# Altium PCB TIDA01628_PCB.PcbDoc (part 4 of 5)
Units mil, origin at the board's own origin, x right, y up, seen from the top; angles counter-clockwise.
Board outline 14212.6 x 5944.88 mil, 4 copper layers (Top Layer, GND, 5V, Bottom Layer), stack 60.8 mil thick; 304 components, 201 nets, 839 pads, 2143 vias.
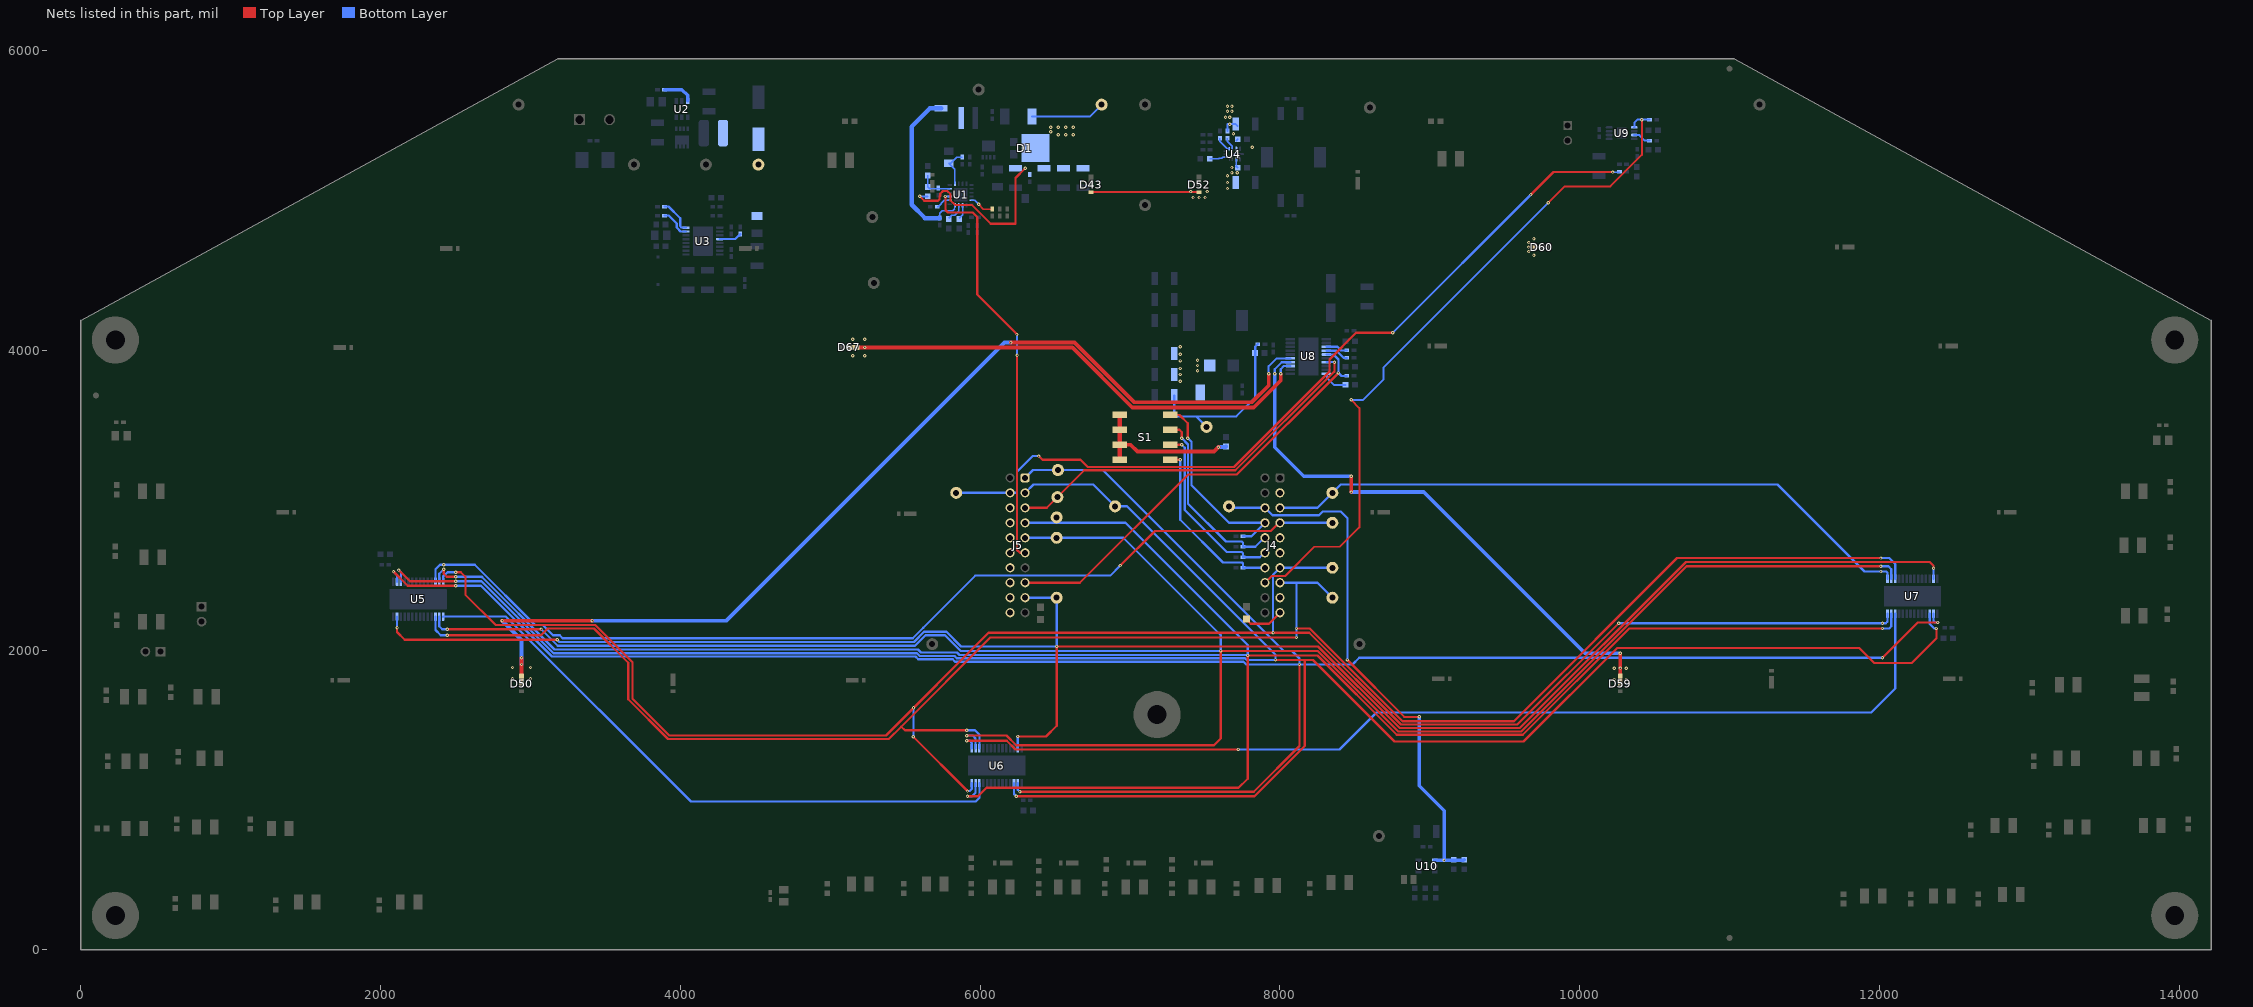
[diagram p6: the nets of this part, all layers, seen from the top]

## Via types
v1: diameter 22, hole 10, Top Layer to Bottom Layer, 1391 vias
v2: diameter 22, hole 10, Top Layer to Bottom Layer, tented both sides, 644 vias
v3: diameter 19.68, hole 7.87, Top Layer to Bottom Layer, tented both sides, 56 vias
v4: diameter 19.68, hole 7.87, Top Layer to Bottom Layer, 47 vias
v5: diameter 19.68, hole 7.87, Top Layer to Bottom Layer, tented top, 5 vias

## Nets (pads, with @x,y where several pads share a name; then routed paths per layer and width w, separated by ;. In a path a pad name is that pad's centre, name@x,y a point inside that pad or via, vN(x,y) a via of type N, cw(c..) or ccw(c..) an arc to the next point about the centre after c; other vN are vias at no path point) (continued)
NetR6_1: R6.1 U1.12 | length 162.2
  Top Layer w10: v2(5990,4975) 6021.38,4943.62 R6.1@6080,4943.62
  Bottom Layer w10: U1.12@5941.85,5001.61 5963.39,5001.61 v2(5990,4975)
NetR8_2: R8.2 U2.3 | length 207.7
  Bottom Layer w23: R8.2@3893.62,5740 4010,5740 4047.4,5702.6 U2.3@4047.4,5664.13
NetR10_2: R10.2 U1.1 | length 101.8
  Bottom Layer w10: R10.2@5713.62,4960 5720,4960 5761.61,5001.61 U1.1@5798.15,5001.61
NetR15_2: R15.2 U3.12 | length 151.7
  Bottom Layer w15: U3.12@4262.2,4742.8 4366.42,4742.8 R15.2@4400,4776.38
NetR17_2: R17.2 U3.7 | length 204.1
  Bottom Layer w15: R17.2@3893.62,4900 3922.3,4900 3975,4847.3 3975,4820 4001.02,4793.98 U3.7@4037.79,4793.98
NetR18_1: R18.1 U4.9 | length 84.3
  Bottom Layer w9: R18.1@7650,5416.38 7650,5395 7682.13,5362.87 U4.9@7682.13,5345.43
NetR67_1: R67.1 U8.4 | length 156.3
  Bottom Layer w15: U8.4@8310.08,3998.39 8376.61,3998.39 8425,3950 R67.1@8446.38,3950
NetR68_2: R68.2 U8.3 | length 146.2
  Bottom Layer w15: U8.3@8310.08,4023.98 8383.98,4023.98 8407.95,4000 R68.2@8446.38,4000
NetR69_1: R69.1 U8.10 | length 174
  Bottom Layer w13: U8.10@8310.08,3844.84 8315,3839.92 8315,3815 8360,3770 R69.1@8438.5,3770
NetR75_2: R75.2 U9.3 | length 118.1
  Bottom Layer w13: U9.3@10363.66,5437.2 10397.8,5437.2 10435,5400 R75.2@10466.38,5400
NetR76_1: R76.1 S1.5 S1.6 S1.7 S1.8 | length 1041.8
  Top Layer w25: S1.7@6930.71,3370 7005,3370 7050,3325 7560,3325 v2(7590,3355)
  Top Layer w30: S1.8@6930.71,3270 S1.7@6930.71,3370 S1.6@6930.71,3470 S1.5@6930.71,3570
  Bottom Layer w25: v2(7590,3355) 7636.5,3355 R76.1@7640,3358.5
NetU5_15: U5.15 U6.12 | length 4199.8
  Bottom Layer w15: U5.15@2416.34,2223.86 2417.48,2225 2835,2225 4070,990 5970,990 5994.84,1014.84 U6.12@5994.84,1113.86
NetU6_15: U6.15 U7.12 | length 6960.8
  Top Layer w15: v2(5910,1395) 6177.65,1395 6235.04,1337.61 v2(7722.61,1337.61)
  Bottom Layer w15: v2(5910,1395) 5930,1395 5943.66,1381.34 U6.15@5943.66,1346.14 ; v2(7722.61,1337.61) 8397.61,1337.61 8645,1585 11945,1585 12104.84,1744.84 12104.84,2134.84 U7.12@12104.84,2243.86
OUT1: D50.2 U8.15 | length 6934.6
  Top Layer w25: v2(2810,2197.13) v2(3410,2197.13) ; D50.2@2940,1803.62 v2(2940,1949) ; v2(6205,4052.87) 6628.62,4052.87 7026.49,3655 7813.51,3655 7925,3766.49 v2(7925,3845)
  Bottom Layer w13: v2(7925,3845) 7925,3895 7977.2,3947.2 U8.15@8069.92,3947.2
  Bottom Layer w25: v2(2810,2197.13) 2940,2067.13 v2(2940,1905) ; v2(3410,2197.13) 4307.13,2197.13 ; 4345,2235 4307.13,2197.13 ; v2(6205,4052.87) 6162.87,4052.87 4307.13,2197.13
  other v2: 2880,1810 3000,1810 2880,1885 3000,1885
OUT2: D59.2 U8.14 | length 3757.2
  Top Layer w25: v2(8475,3055) v2(8475,3160) ; D59.2@10270,1803.62 v2(10270,1980)
  Bottom Layer w15: v2(7965,3845) 7965,3875 8011.61,3921.61 U8.14@8069.92,3921.61
  Bottom Layer w25: v2(7965,3845) 7965,3354 8159,3160 v2(8475,3160) ; v2(8475,3055) 8960,3055 10035,1980 v2(10270,1980)
  other v2: 10230,1805 10310,1805 10230,1880 10270,1880.81 10310,1880
OUT3: D67.2 U8.13 | length 3240.3
  Top Layer w25: D67.2@5153.62,4020 6205,4020 6615,4020 7015,3620 7825,3620 8005,3800 v2(8005,3845)
  Bottom Layer w15: v2(8005,3845) 8005,3875 8026.02,3896.02 U8.13@8069.92,3896.02
  other v2: 5150,3965 5230,3965 5230,4020 5150,4075 5230,4075
P1.2_STA: J5.11 U1.2 | length 2741.9
  Top Layer w15: v2(5767.8,5027.2) 5767.8,4937.2 5785,4920 5950,4920 5980,4890 5980,4374 v2@6245.89,4108.11 ; v2(6246,3967.87) 6245.89,2669.11 6265,2650 J5.11@6300,2650
  Bottom Layer w11: v2(5767.8,5027.2) U1.2@5798.15,5027.2
  Bottom Layer w15: v2@6245,3968.87 v2(6245,4105.87)
P1.3_RCK: J5.9 TP16.1 U5.16 U6.16 U7.16 | length 14767.4
  Top Layer w15: v2(2445,2140) v2@3071.3,2140 ; v2(5910,1430) 6175,1430 6240,1365 7560,1365 7605,1410 v2(7605,1995) 8252.35,1995 8789.47,1457.87 9610.53,1457.87 10712.65,2560 v2(12010,2560)
  Bottom Layer w15: U5.16@2390.75,2223.86 2390.75,2159.25 2410,2140 v2(2445,2140) ; v2@3071.3,2140 3181.3,2030 5565,2030 5635,2100 5765,2100 5870,1995 v2(7605,1995) 7605,2100 6955,2750 TP16.1@6510,2750 J5.9@6300,2750 ; v2(5910,1430) 5950,1430 5969.25,1410.75 U6.16@5969.25,1346.14 ; v2(12010,2560) 12060,2560 12079.25,2540.75 U7.16@12079.25,2476.14
  other v2: 3070,2141.3
P1.4_CLR: J5.7 TP19.1 U5.13 U6.13 U7.13 | length 15469
  Top Layer w15: v2(2420,2540) 2420,2510 2440,2490 v2(2500,2490) ; v2(5915,1025) 5985,1025 6041.37,1081.37 7723.5,1081.37 7785,1142.87 v2(7785,1965) 8250,1965 8780,1435 9620,1435 10330,2145 v2(12020,2145)
  Bottom Layer w15: U5.13@2390.75,2456.14 2390.75,2510.75 v2(2420,2540) ; v2(2500,2490) 2674.7,2490 ; 2679.7,2485 2674.7,2490 ; v2(5915,1025) 5945,1025 5969.25,1049.25 ; 5969.25,1047.72 5969.25,1049.25 ; 5969.25,1070 5969.25,1049.25 ; U6.13@5969.25,1113.86 5969.25,1049.25 ; J5.7@6300,2850 TP19.1@6505,2850 ; TP19.1@6510,2910 6510,2855 TP19.1@6505,2850 ; v2(12020,2145) 12065,2145 12079.25,2159.25 U7.13@12079.25,2243.86 ; 2674.7,2490 3159.7,2005 5585,2005 5605.37,1984.63 5845.37,1984.63 5861.37,1968.63 7781.37,1968.63 v2(7785,1965) 7785,2035 6970,2850 TP19.1@6505,2850
P1.5_PWM_BL: J5.5 TP26.1 U8.7 | length 2556.2
  Top Layer w15: J5.5@6300,2950 6444,2950 TP26.1@6515,3021 6694,3200 7702.35,3200 8360.73,3858.39 8363.39,3858.39 v2(8363.39,3921.61)
  Bottom Layer w13: U8.7@8310.08,3921.61 v2(8363.39,3921.61)
P1.6: J4.9
P2.0_PWM_aud: J5.4 R74.1 TP27.1 | length 5497.9
  Top Layer w15: v2(6390,3295) 6415,3270 6670,3270 6717.13,3222.87 7692.87,3222.87 8330,3860 8330,3940 8507.82,4117.82 v2(8752.82,4117.82) ; v2(9675,5040) 9825,5190 v2(10220,5190)
  Bottom Layer w10: v2(10220,5190) 10264.38,5190 R74.1@10265.38,5191
  Bottom Layer w15: TP27.1@5840,3050 J5.4@6200,3050 6240,3050 6245.89,3055.89 6245.89,3190.89 6350,3295 v2(6390,3295) ; v2(8752.82,4117.82) v2(9675,5040)
P2.2: J5.6
P2.3: J5.18
P2.4_G2: J5.3 TP23.1 U5.3 U6.3 U7.3 | length 16331
  Top Layer w15: v2(2120,2535) 2195,2460 v2(2500,2460) ; v2(6240,1025) 7830,1025 8165,1360 8165,1935 ; v2(7970,1935) 8165,1935 ; v2(12380,2145) 12380,2080 12215,1915 11965,1915 11865,2015 10250,2015 9625,1390 8765,1390 8220,1935 8165,1935
  Bottom Layer w15: v2(2120,2535) 2134.84,2520.16 U5.3@2134.84,2456.14 ; v2(2500,2460) 2672.35,2460 3152.35,1980 5577.65,1980 5595.9,1961.75 5828.25,1961.75 5844.25,1945.75 7766.95,1945.75 7777.7,1935 v2(7970,1935) 7970,1970 6980,2960 TP23.1@6900,2960 6755,3105 6355,3105 J5.3@6300,3050 ; U6.3@6225.16,1113.86 6225.16,1039.84 v2(6240,1025) ; 12335.16,2195 12335.16,2174.84 ; U7.3@12335.16,2243.86 12335.16,2174.84 ; v2(12380,2145) 12365,2145 12335.16,2174.84
P2.5_G1: J5.1 TP22.1 U5.2 U6.2 U7.2 | length 15912.3
  Top Layer w15: v2(2085,2525) 2180,2430 v2(2500,2430) ; v2(6265,1055) 7825,1055 8130,1360 v2(8130,1905) ; v2(12020,1950) 12255,2185 v2(12390,2185)
  Bottom Layer w15: v2(2085,2525) 2109.25,2500.75 U5.2@2109.25,2456.14 ; v2(2500,2430) 2670,2430 3142.87,1957.13 5567.87,1957.13 5586.12,1938.88 5816.12,1938.88 5832.12,1922.88 7757.47,1922.88 7775.35,1905 ; U6.2@6250.75,1113.86 6250.75,1069.25 v2(6265,1055) ; J5.1@6300,3150 6352,3202 TP22.1@6519,3202 6818,3202 8025,1995 8080,1995 8130,1945 v2(8130,1905) ; 7835,1905 7775.35,1905 ; v2(12020,1950) 8529.87,1950 8484.87,1905 v2(8130,1905) ; U7.2@12360.75,2243.86 12360.75,2194.25 12370,2185 v2(12390,2185) ; 7775.35,1905 v2(8130,1905)
P2.6: J5.16
P2.7_SRCK: J4.15 TP18.1 U5.17 U6.17 U7.17 | length 12802.8
  Top Layer w15: v2(2445,2100) 3070,2100 3114.8,2144.8 3422.85,2144.8 3652.21,1915.44 3652.21,1672.21 3916.55,1407.87 5390.53,1407.87 5472.65,1490 ; v2(5910,1465) 5497.65,1465 5472.65,1490 ; v2(8110,2085) 6067.65,2085 5472.65,1490 ; v2(8110,2145) 8199.39,2145 8817.9,1526.5 9561.5,1526.5 10650,2615 v2(12010,2615)
  Bottom Layer w15: U5.17@2365.16,2223.86 2365.16,2134.84 2400,2100 v2(2445,2100) ; v2(5910,1465) 5965,1465 5994.84,1435.16 U6.17@5994.84,1346.14 ; J4.15@8000,2450 8250,2450 TP18.1@8350,2350 ; v2(8110,2085) v2(8110,2145) 8110,2450 ; v2(12010,2615) 12065,2615 12104.84,2575.16 U7.17@12104.84,2476.14
P3.0: J5.12
P3.1: J5.14
P3.2_EN: J4.13 TP15.1 U5.14 U6.14 U7.14 | length 12808.2
  Top Layer w15: v2(2500,2520) 2535,2520 2565,2490 2565,2370 2767.33,2167.67 3187.03,2167.67 3432.33,2167.67 3680,1920 3680,1676.77 3926.02,1430.75 5370.75,1430.75 6055.89,2115.89 v2(7954.11,2115.89) 8196.16,2115.89 8808.42,1503.62 9583.62,1503.62 v2(10260,2180) ; v2(5552.5,1422.5) v2(5915,1060)
  Bottom Layer w15: U5.14@2416.34,2456.14 2416.34,2491.34 2445,2520 v2(2500,2520) ; v2(5552.5,1422.5) 5555,1425 v2(5555,1615) ; v2(5915,1060) 5930,1060 5943.66,1073.66 U6.14@5943.66,1113.86 ; v2(7954.11,2115.89) 7954.11,2504.11 ; 7955,2505 7954.11,2504.11 ; TP15.1@8350,2550 J4.13@8000,2550 7954.11,2504.11 ; v2(10260,2180) v2(12020,2180) 12042.32,2180 12053.66,2191.34 U7.14@12053.66,2243.86
P3.3_SER_IN: J4.7 TP17.1 U5.12 | length 6603.3
  Top Layer w15: v2(6935,2565) 7165.89,2795.89 7939.11,2795.89 7993.23,2850 J4.7@8000,2850
  Bottom Layer w15: U5.12@2365.16,2456.14 2365.16,2540.16 2395,2570 v2(2420,2570) 2627.05,2570 3029.37,2167.67 3080.92,2167.67 3149.3,2099.3 3194.3,2099.3 3213.6,2080 5550.3,2080 5620,2149.7 5620,2150 5967.5,2497.5 6867.5,2497.5 v2(6935,2565) ; J4.7@8000,2850 TP17.1@8350,2850
P3.4: J4.5 TP20.1 U7.15 | length 4401.9
  Bottom Layer w15: J4.5@8000,2950 8250,2950 TP20.1@8350,3050 8405,3105 11320,3105 11900,2525 v2(12010,2525) 12045,2525 12053.66,2516.34 U7.15@12053.66,2476.14
P3.7_ERR: J5.17 TP21.1 U5.27 U6.27 U7.27 | length 12666.8
  Top Layer w15: v2(2109.25,2149.25) 2109.25,2120.75 2160,2070 v2(3178.6,2070) ; v2(6250.75,1424.25) 6439.25,1424.25 6510,1495 v2(6510,2025) 8254.7,2025 8798.95,1480.75 9600.75,1480.75 10708.63,2588.63 12336.37,2588.63 12360.75,2564.25 v2(12360.75,2545.75)
  Bottom Layer w15: v2(2109.25,2149.25) U5.27@2109.25,2223.86 ; v2(3178.6,2070) 3193.6,2055 5557.65,2055 5625.53,2122.87 5774.47,2122.87 5872.35,2025 v2(6510,2025) ; U6.27@6250.75,1346.14 v2(6250.75,1424.25) ; J5.17@6300,2350 TP21.1@6510,2350 v2(6510,2025) ; v2@6510,2022.87 v2(6510,2025) ; U7.27@12360.75,2476.14 v2(12360.75,2545.75)
P4.0_Fau_BL: J5.15 R70.2 U8.5 | length 2918.1
  Top Layer w15: J5.15@6300,2450 6665,2450 7387.5,3172.5 7712.5,3172.5 v2(8390,3850)
  Bottom Layer w15: U8.5@8310.08,3972.8 8357.2,3972.8 8390,3940 v2(8390,3850) 8410,3830 R70.2@8446.38,3830
P4.1: D69.1 J4.19 | length 265.6
  Top Layer w15: D69.1@7776.77,2206.23 7806,2177 7927,2177 J4.19@8000,2250
P4.2: J4.17
P6.0_ADC: C67.1 J4.6 R71.2 TP29.1 U10.1 | length 3644.8
  Top Layer w15: v2(8450,1935) 8830,1555 v2(8930,1555)
  Bottom Layer w15: TP29.1@7660,2960 7670,2950 J4.6@7900,2950 7950,2900 8260,2900 8285,2925 8405,2925 8450,2880 v2@8450,1940
  Bottom Layer w23: v2(8930,1555) 8930,1095 9095,930 v2(9095,597.4) ; U10.1@9032.83,597.4 v2(9095,597.4) ; C67.1@9228.7,601.5 9224.61,597.4 v2(9095,597.4)
P6.1_Beam: J4.8 R79.2 S1.4 | length 1341.1
  Top Layer w15: S1.4@7269.29,3570 7330,3570 7385,3515 v2(7385,3415)
  Bottom Layer w15: v2(7385,3415) 7410,3390 7410,3100 7660,2850 J4.8@7900,2850 7810,2760 R79.2@7753.62,2760
P6.2_Dir_L: J4.10 R80.2 S1.3 | length 1256
  Top Layer w15: S1.3@7274.29,3475 S1.3@7269.29,3470 7330,3470 7345,3455 v2(7345,3415)
  Bottom Layer w15: v2(7345,3415) 7387.13,3372.87 7387.13,2977.87 7640,2725 7745,2725 7753.62,2716.38 R80.2@7753.62,2690 7835,2690 7895,2750 J4.10@7900,2750
P6.3_Belt: J4.12 R81.2 S1.2 | length 1212.3
  Top Layer w15: S1.2@7269.29,3370 v2(7345,3370)
  Bottom Layer w15: v2(7345,3370) 7364.25,3350.75 7364.25,2935.75 7645,2655 7745,2655 7753.62,2646.38 R81.2@7753.62,2620 7865,2620 7895,2650 J4.12@7900,2650
P6.4_R: J4.14 R82.2 S1.1 | length 1180
  Top Layer w15: S1.1@7269.29,3270 v2(7335,3270)
  Bottom Layer w15: v2(7335,3270) 7335,2870 7620,2585 7747.24,2585 7753.62,2578.62 R82.2@7753.62,2550 J4.14@7900,2550
P6.5: J4.3
P6.6: J4.11
P7.0_SHUTDOWN: J4.16 R72.1 U9.1 | length 4697
  Top Layer w13: J4.16@7900,2450 7945,2495 8035,2495 8230,2690 8400,2690 8530,2820 8530,3615 v2(8475,3670) ; v2(9790,4985) 9900,5095 10205,5095 10415,5305 v2(10415,5540)
  Bottom Layer w13: v2(8475,3670) 8555,3670 8690,3805 8690,3885 v2(9790,4985) ; U9.1@10363.66,5488.39 10366,5490.72 10366,5521 10385,5540 R72.1@10466.38,5540
P7.4: J5.8
P8.1: J5.20
PG_3V3: R22.1 U3.8 | length 233.2
  Bottom Layer w15: R22.1@3893.62,4960 3920,4960 3997.87,4882.13 3997.87,4829.47 4007.78,4819.57 U3.8@4037.79,4819.57
PG_5V: R21.1 U4.8 | length 104.4
  Bottom Layer w9: R21.1@7600,5416.38 7600,5395 7648.02,5346.98 7650.67,5346.98 7652.21,5345.43 U4.8@7662.44,5345.43
PVCC: C16.1 R9.2 U1.5 | length 262
  Bottom Layer w10: U1.5@5831.61,5111.85 5831.61,5208.39 C16.1@5790,5250 5805,5250 5845,5290 R9.2@5880,5290
RST: J5.10
RT: R11.2 U1.14 | length 96.1
  Bottom Layer w10: R11.2@5860,4881.5 5882.8,4904.29 U1.14@5882.8,4968.15
V_backlight: C58.1 C59.1 C60.1 C61.1 D43.1 D51.1 D52.1 D60.1 R64.2 R65.2 TP25.1 | length 1908.2
  Top Layer w15: D43.1@6740,5056.85 D52.1@7460,5056.85
  Bottom Layer w15: C58.1@7294.96,3700 7294.96,3571.04 7306,3560 7440,3560 ; TP25.1@7510,3490 7440,3560 ; R65.2@7852.38,4042.8 7834.5,4024.93 C61.1@7834.5,3982.8 7834.5,3686.5 7708,3560 7440,3560
  other v2: 7335,3795 7335,3840 7450,3865 7335,3880 7450,3900 7335,3930 7450,3935 7335,3975 7335,4025 9695,4635 9660,4660 9660,4690 9660,4720 9695,4745 7420,5020 7460,5020 7500,5020 7405,5060 7515,5060
VBOOST: C3.1 C4.1 C5.1 C6.1 C7.1 C29.1 C30.1 C31.1 C32.1 D1.3 R1.2 R7.2 R18.2 TP2.1 U4.2 U4.10 | length 1958.4
  Top Layer w12: 5801,5002.35 5801,5044.6
  Top Layer w15: v2(5596.5,5028.5) 5626.02,4998.98 5718.98,4998.98 5728,5008 5728,5026.5 5733.03,5031.53 5733.03,5045.82 5751.2,5064 5780.6,5064 5800,5044.6 ; 5800,5002.35 5831.12,4971.22 5943.78,4971.22 6070,4845 6235,4845 6235,5150 v2(6300,5215)
  Bottom Layer w10: C30.1@7708.7,5229.8 U4.2@7708.7,5274.57
  Bottom Layer w13: v2(5596.5,5028.5) R7.2@5650,5028.5 ; R1.2@6345.67,5560 6730,5560 TP2.1@6810,5640 ; R18.2@7650,5463.62 7650,5510 C31.1@7705.04,5510 C31.1@7718.5,5496.54 ; C30.1@7705.04,5226.14 7708.7,5229.8 C30.1@7718.5,5220 ; C32.1@7708.7,5400.2 C32.1@7718.5,5410
  other v2: 7650,5080 7650,5120 7650,5165 7680,5185 7715,5185 7680,5220 7815,5355 6520,5440 6570,5440 6620,5440 7690,5445 6470,5460 6470,5490 6520,5490 6570,5490 6620,5490 7665,5510 7637,5555 7665,5555 7650,5595 7680,5595 7650,5630 7680,5630
VCC_5V: C40.1 U4.5 | length 107.7
  Bottom Layer w9: C40.1@7531.5,5280 7591.94,5280 7595.32,5283.37 7611.43,5283.37 7618.37,5290.31 U4.5@7634.88,5290.31
VIN: C8.1 C12.1 C13.1 L1.1 L2.2 R14.1 TP5.1 U1.16 | length 1160.1
  Bottom Layer w7: 5831.61,4944.53 U1.16@5831.61,4968.15
  Bottom Layer w9: 5818.37,4931.28 5831.61,4944.53
  Bottom Layer w10: C13.1@5730,4883.62 5730,4915 5746.28,4931.28 5818.37,4931.28
  Bottom Layer w30: C13.1@5730,4883.62 5631.38,4883.62 5544,4971 5544,5494 5664.96,5614.96 C12.1@5740,5614.96
Vout: C17.2 R5.1 R7.1 U1.4 | length 230.6
  Bottom Layer w10: C17.2@5650,5168.5 R7.1@5650,5091.5 5663.11,5078.39 U1.4@5798.15,5078.39
VSET: R12.2 U1.15 | length 125.9
  Bottom Layer w10: R12.2@5790,4881.5 5811.5,4903 5829.91,4903 5835.97,4909.06 5837.06,4909.06 5857.2,4929.2 U1.15@5857.2,4968.15
pads on no net: D3. D4. D5. D6. D43. D44. D45. D46. D47. D48. D49. D50. D52. D53. D54. D55. D56. D57. D58. D59. D60. D61. D62. D63. D64. D65. D66. D67. FID1.1 FID2.1 FID3.1 H6.0 H7.0 H8.0 H9.0 H10.0 J4.18 J4.20 J5.13 LBL1.0 U1.6 U1.8 U1.17@5845.98,5015.98 U1.17@5845.98,5064.02 U1.17@5894.02,5015.98 U1.17@5894.02,5064.02 U1.A1 U1.A2 U1.A3 U1.A4 U3.17@4150,4730 U4.3 U4.12@7701.02,5310 U4.12@7740.98,5310 U5.29@2250,2340 U6.29@6110,1230 U7.24 U7.25 U7.29@12220,2360 U8.8 U8.19 U8.21@8190,3960

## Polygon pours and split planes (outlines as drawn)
5V on Bottom Layer "BOTTOM_LAYER_5V_P022" (solid, remove dead copper, pour order 22): 8370,4069.82 8370,4400 8035,4400 8035,4070 8103.05,4070 8105,4071.95 8105,4100 8280,4100 8280,4070.37
V_backlight on Bottom Layer "BOTTOM_LAYER_V_BACKLIGHT_P014" (solid, remove dead copper, pour order 14): 7618.37,5062.28 7610.65,5070 6675,5070
5V on Bottom Layer "BOTTOM_LAYER_5V_P021" (solid, remove dead copper, pour order 21): 8075,5720 8075,4765 8710,4765 8710,5720
VIN on Bottom Layer "BOTTOM_LAYER_VIN_P015" (solid, remove dead copper, pour order 15): 5895,5475 5800,5475 5800,5555 5685,5555 5685,5650 5895,5650
NetC1_2 on Bottom Layer "BOTTOM_LAYER_NETC1_2_P016" (solid, remove dead copper, pour order 16): 5935,5640 6030,5640 6030,5565 6100,5565 6100,5325 5935,5325
NetC1_2 on Bottom Layer "BOTTOM_LAYER_NETC1_2_P017" (solid, remove dead copper, pour order 17): 6250,5280 6250,5435 6090,5435 6090,5318.31 6124.65,5318.31 6124.65,5280
VBOOST on Bottom Layer "BOTTOM_LAYER_VBOOST_P018" (solid, remove dead copper, pour order 18): 6740,5290 6640,5390 6640,5625 6280,5625 6280,5255.51 6185,5255.51 6185,5155 6740,5155
NetQ2_1 on Bottom Layer "BOTTOM_LAYER_NETQ2_1_P019" (solid, remove dead copper, pour order 19): 6155,5180 6050,5180 6050,5245 6035,5260 6035,5303.7 6036.42,5305.12 6115,5305 6115,5275 6120,5270 6155,5270
GND on Bottom Layer "BOTTOM_LAYER_GND_P027" (solid, remove dead copper, pour order 27): 6265,4970 6265,5105 6665,5105 6665,4970
GND on Bottom Layer "BOTTOM_LAYER_GND_P025" (solid, remove dead copper, pour order 25): 5955,5055 5970,5055 6035,5120 6287.35,5120 6290.24,5117.11 6290,5116.87 6290,5035 5975,5035 5970,5040 5955,5040
VIN on Bottom Layer "BOTTOM_LAYER_VIN_P020" (solid, remove dead copper, pour order 20): 5885,5645 4225,5645 4225,5340 4440,5125 4440,4875 4475,4875 4540,4810 5845,4810 5845,5405 5895,5455 5895,5650
KL30_Power on Bottom Layer "BOTTOM_LAYER_KL30_POWER_P013" (solid, remove dead copper, pour order 13): 3420,5770 3420,5195 3780,5195 3780,5455 3924.06,5455 4035,5455 4035,5580 4010,5605 3875,5605 3875,5765 3870,5770
AGND on Bottom Layer "BOTTOM_LAYER_AGND_P024" (solid, remove dead copper, pour order 24): 5661.84,4853.71 5660,4851.88 5660,4725 6375,4725 6375,5020 6235,5020 6210,5020 6190,5040 5974.05,5040 5962.6,5028.56 5938.41,5028.56 5938.41,5024.36 5933.85,5019.8 5973.05,4980.6 6026.16,4980.6 6026.16,4855.58
NetD52_2 on Bottom Layer "BOTTOM_LAYER_NETD52_2_P023" (solid, remove dead copper, pour order 23): 7390,5085 7390.68,5085.68 7540.68,5085.68 7540.68,5239.32 7540,5240 7390,5240
GND on Bottom Layer "BOTTOM_LAYER_GND_P029" (solid, remove dead copper, pour order 29): 0,0 0,4200 9,4200 1753.88,5944.88 11046.88,5944.88 14216,5944.88 14216,3.4 14212.6,0
5V on 5V "5V_5V_P012" (solid, remove dead copper, pour order 12): 0,0 0,4200 9,4200 1753.88,5944.88 11046.88,5944.88 14216,5944.88 14216,3.4 14212.6,0
VBOOST on 5V "5V_VBOOST_P011" (solid, remove dead copper, pour order 11): 7632.18,5651.82 7849.91,5651.82 7849.91,5066.82 7627.27,5066.82
GND on GND "GND_GND_P010" (solid, remove dead copper, pour order 10): 0,0 0,4200 9,4200 1753.88,5944.88 11046.88,5944.88 14216,5944.88 14216,3.4 14212.6,0
NetD44_2 on Top Layer "TOP_LAYER_NETD44_2_P002" (solid, remove dead copper, pour order 2): 5610,5140 5885,5140 5890,5135 5890,4968.19 5610,4968.19
NetD43_2 on Top Layer "TOP_LAYER_NETD43_2_P004" (solid, remove dead copper, pour order 4): 6810,5240 6810,5090 6532.91,5090 6530,5092.91 6532.6,5095.51 6532.6,5240
GND on Top Layer "TOP_LAYER_GND_P009" (solid, remove dead copper, pour order 9): 0,0 0,4200 9,4200 1753.88,5944.88 11046.88,5944.88 14216,5944.88 14216,3.4 14212.6,0
VBOOST on Top Layer "TOP_LAYER_VBOOST_P007" (solid, remove dead copper, pour order 7): 7635,5060 7745.12,5060 7840,5154.88 7840,5255 7855,5255 7885,5285 7885,5400 7855,5400 7755,5500 7755,5790 6300,5790 6300,5315 6810,5315 6885,5240 7620,5240 7620,5200 7635,5185
V_backlight on Top Layer "TOP_LAYER_V_BACKLIGHT_P000" (solid, remove dead copper, pour order 0): 6535,5075 6535,4551.45 7133.55,4551.45 7180,4505 7175,4500 7175,3680 8120,3680 8610,4170 9410,4170 9715,4475 9715,4840 9605,4950 7695,4950 7635,5010 7635,5075
NetD44_2 on Top Layer "TOP_LAYER_NETD44_2_P005" (solid, remove dead copper, pour order 5): 5610,4968.19 5810,4968.19 5810,5145 5610,5145
AGND on Top Layer "TOP_LAYER_AGND_P008" (solid, remove dead copper, pour order 8): 6010,5283.07 6010,5010 5950.71,5010 5950,5010.71 5950,5285 6009.84,5285
NetD43_2 on Top Layer "TOP_LAYER_NETD43_2_P006" (solid, remove dead copper, pour order 6): 6535,5085 6535.04,5085.04 6806.86,5085.04 6806.86,5238.19 6803.67,5235 6535,5235

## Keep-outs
Keep-Out Layer:
  text ".Layer_Name" at 577,-858.49 h60

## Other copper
Top Layer:
  rectangle net L29: 4915,5190 5053.43,5354.33
  rectangle net NetD23_1: 5075,5190 5200,5354.33
  rectangle net NetD40_1: 8999.84,5190 9135,5354.33
  rectangle net L28: 9150,5190 9290,5354.33
  rectangle net NetD54_2: 12330,3828.19 12425,4101.19
  rectangle net NetD55_2: 12435,3829.19 12610,4100
  rectangle net NetD53_2: 11631.81,4486.93 11730,4760
  rectangle net NetD54_2: 11745,4490 11911.81,4766.07
  rectangle net NetD55_2: 12711.81,2719.45 12815,2992.45
  rectangle net NetD56_2: 12825,2720.45 12991.81,2991.26
  rectangle net NetD57_2: 12341.81,1609.45 12515,1882.45
  rectangle net NetD56_2: 12525,1610.45 12621.81,1881.26
  region net NetD57_2: 11071.26,1918.19 11071.26,1845 11344.26,1845 11344.26,1918.19
  region net NetD58_2: 11072.26,1835 11072.26,1645 11350,1645 11350,1835
  rectangle net OUT2: 10201.81,1760 10480,1922.45
  rectangle net NetD58_2: 10200,1650.45 10481.81,1745
  rectangle net NetD63_2: 8930,1608.19 9105,1881.19
  rectangle net NetD62_2: 9115,1609.19 9210,1880
  rectangle net NetD61_2: 8551.81,2719.45 8635,2992.45
  rectangle net NetD62_2: 8645,2716.93 8831.81,2991.26
  rectangle net NetD60_2: 8931.81,3829.45 9015,4102.45
  rectangle net NetD61_2: 9025,3830.45 9211.81,4101.26
  rectangle net V_backlight: 9640.81,4488.26 9715,4761.26
  rectangle net NetD60_2: 9725,4489.26 9920.81,4760.07
  region net NetD52_2: 8303.86,5238.19 8303.86,5175 8576.86,5175 8576.86,5238.19
  region net NetD53_2: 8304.86,5165 8304.86,4966.93 8575.67,4966.93 8575.67,5165
  region net NetD52_2: 7393.86,5238.19 7393.86,5085 7580,5085 7580,5238.19
  region net V_backlight: 7394.86,5075 7394.86,4966.93 7575,4966.93 7575,5075
  region net V_backlight: 6534.86,5075 6534.86,4966.93 6805.67,4966.93 6805.67,5075
  region net NetD43_2: 5611.26,5238.19 5611.26,5160 5884.26,5160 5884.26,5238.19
  rectangle net NetD45_2: 4301.81,4489.45 4480,4762.45
  rectangle net NetD44_2: 4495,4490.45 4580,4761.26
  rectangle net NetD66_2: 5001.81,3829.45 5090,4102.45
  rectangle net OUT3: 5105,3830.45 5281.81,4101.26
  rectangle net NetD65_2: 5381.81,2719.45 5475,2992.45
  rectangle net NetD66_2: 5485,2720.45 5661.81,2991.26
  rectangle net NetD64_2: 5010,1608.19 5190,1881.19
  rectangle net NetD63_2: 5210,1609.19 5290,1880
  region net NetD65_2: 3743.86,1918.19 3743.86,1760 4016.86,1760 4016.86,1918.19
  region net NetD64_2: 3744.86,1740 3744.86,1645 4015.67,1645 4015.67,1740
  region net OUT1: 2871.26,1918.19 2871.26,1755 3144.26,1755 3144.26,1918.19
  region net NetD49_2: 2872.26,1740 2872.26,1645 3143.07,1645 3143.07,1740
  rectangle net NetD48_2: 1601.81,1609.45 1691,1882.45
  rectangle net NetD49_2: 1711,1610.45 1881.81,1881.26
  rectangle net NetD48_2: 1220,2718.19 1392,2991.19
  rectangle net NetD47_2: 1601.81,3829.45 1772,4102.45
  rectangle net NetD46_2: 1789,3830.45 1881.81,4101.26
  rectangle net NetD46_2: 2311.81,4489.45 2480,4762.45
  rectangle net NetD45_2: 2500,4490.45 2591.81,4761.26
  rectangle net L26: 13501.26,2621.26 13670,2790
  rectangle net NetD41_1: 13710,2622.26 13860,2790
  rectangle net L27: 13501.81,2971.26 13680,3244.26
  rectangle net NetD31_1: 13725,2972.26 13860,3243.07
  region net NetD39_1: 13894.33,1640 13894.33,1730 13621.33,1730 13621.33,1640
  region net L24: 13893.33,1770 13893.33,1970 13622.52,1970 13622.52,1770
  rectangle net L25: 13511.81,2141.26 13680,2410
  rectangle net NetD22_1: 13725,2142.26 13870,2413.07
  rectangle net NetD21_1: 13091.26,1691.26 13245,1890
  rectangle net L23: 13280,1692.26 13450,1890
  rectangle net L22: 13631.81,1202.52 13759.15,1475.52
  rectangle net NetD13_1: 13780.15,1203.52 13911.81,1474.33
  rectangle net NetD38_1: 13091.81,1201.26 13219.15,1474.26
  rectangle net L21: 13240.15,1202.26 13450,1473.07
  rectangle net L20: 13641.81,741.26 13805,1014.26
  rectangle net NetD30_1: 13840,742.26 14000,1013.07
  rectangle net NetD20_1: 13201.81,742.52 13329.15,1015.52
  rectangle net L19: 13350.15,743.52 13481.81,1014.33
  rectangle net NetD37_1: 12681.26,741.26 12808.6,1014.26
  rectangle net L18: 12829.6,742.26 13040,1013.07
  rectangle net NetD12_1: 12741.81,282.52 12869.15,555.52
  rectangle net L17: 12890.15,283.52 13021.81,554.33
  rectangle net NetD19_1: 12291.81,282.52 12419.15,555.52
  rectangle net L16: 12440.15,283.52 12571.81,554.33
  rectangle net NetD36_1: 11831.81,282.52 11959.15,555.52
  rectangle net L13: 11980.15,283.52 12111.81,554.33
  rectangle net NetD33_1: 228.66,1170 356,1443
  rectangle net D5: 377,1171 508.66,1441.81
  rectangle net D10: 378.81,722.26 510.47,993.07
  rectangle net D11: 230.47,721.26 357.81,994.26
  rectangle net D14: 858.81,242.26 990.47,513.07
  rectangle net D15: 710.47,241.26 837.81,514.26
  rectangle net D9: 858.81,722.26 990.47,993.07
  rectangle net NetD11_1: 710.47,721.26 837.81,994.26
  rectangle net D12: 1347,722.26 1478.66,993.07
  rectangle net D13: 1198.66,721.26 1326,994.26
  rectangle net D8: 858.81,1179.26 990.47,1450.07
  rectangle net NetD28_1: 710.47,1178.26 837.81,1451.26
  rectangle net D6: 857,1602.26 988.66,1873.07
  rectangle net D7: 708.66,1601.26 836,1874.26
  rectangle net D4: 378.81,1603.52 510.47,1874.33
  rectangle net NetD15_1: 230.47,1602.52 357.81,1875.52
  rectangle net NetD7_2: 468.81,2073.52 670,2390
  rectangle net D3: 320.47,2072.52 447.81,2390
  rectangle net D1: 467,2512.26 670,2830
  rectangle net NetD10_1: 318.66,2511.26 446,2829
  rectangle net D0: 467,2952.26 668,3270
  rectangle net NetD32_1: 318.66,2951.26 446,3269
  rectangle net L0: 1528.81,243.52 1660.47,514.33
  rectangle net NetD24_1: 1380.47,242.52 1507.81,515.52
  rectangle net L1: 2218.81,243.52 2350.47,514.33
  rectangle net NetD42_1: 2070.47,242.52 2197.81,515.52
  rectangle net L2: 5200.15,352.26 5410,623.07
  rectangle net NetD14_1: 5051.81,351.26 5179.15,624.26
  rectangle net L3: 5718.34,352.26 5850,623.07
  rectangle net NetD29_1: 5570,351.26 5697.34,624.26
  rectangle net L5: 6160.15,353.52 6291.81,482.99
  rectangle net NetD16_1: 6011.81,352.52 6139.15,482.99
  rectangle net L7: 6610.15,350.45 6741.81,482.99
  rectangle net NetD34_1: 6461.81,349.45 6589.15,482.99
  rectangle net L9: 7050.15,353.52 7181.81,482.99
  rectangle net NetD17_1: 6901.81,352.52 7029.15,479.06
  rectangle net L11: 7490,353.52 7631.81,482.99
  rectangle net NetD6_1: 7351.81,540.63 7450,625.52
  rectangle net L12: 7938.34,352.26 8070,623.07
  rectangle net NetD18_1: 7790,351.26 7917.34,624.26
  rectangle net L14: 8420.15,353.52 8551.81,624.33
  rectangle net L15: 8271.81,352.52 8399.15,625.52
  rectangle net L4: 6130,540 6290,623.07
  rectangle net NetD3_1: 6010,540 6115,623.07
  rectangle net L6: 6570,535 6740,620
  rectangle net NetD4_1: 6462.6,540.63 6555,620
  rectangle net L8: 7015,540.63 7180,623.07
  rectangle net NetD5_1: 6902.6,540.63 7005,623.07
  rectangle net L10: 7470,540 7630,623.07
  rectangle net NetD35_1: 7350,350 7460,485
  rectangle net NetD47_2: 1409,2719.19 1500,2990
  text ".Layer_Name" at 577,-858.49 h60
Bottom Layer:
  rectangle net NetD43_2: 5677.2,5160 5750,5240
  rectangle net NetD56_2: 12525,1608.19 12620,1880
  rectangle net NetD57_2: 12342.6,1609.45 12515,1880
  rectangle net NetD52_2: 7393.86,5180.28 7446.81,5238.19
  rectangle net NetD52_2: 7393.86,5085 7580,5190
  rectangle net NetD45_2: 2500,4490 2590,4760
  rectangle net NetD46_2: 2310,4490 2480,4760
  rectangle net GND: 5750,5333 5819,5392
  rectangle net GND: 5694,5430 5785,5495
  rectangle net GND: 8038,3844.84 8080,3875
  rectangle net VBOOST: 7615,5500 7698.16,5661.45
  rectangle net NetQ2_1: 6036.42,5272.44 6099.41,5305.12
  rectangle net KL30_Power: 3950,5485.94 3981.84,5597.13
  rectangle net KL30_Power: 3993.15,5465 4024,5493
  rectangle net AGND: 6240,4975 6375,5015
  rectangle net NetD47_2: 1600,3830 1773.55,4100
  rectangle net NetD46_2: 1790,3826.93 1880,4100
  rectangle net NetD48_2: 1215,2716.93 1395,2990
  rectangle net NetD47_2: 1409,2720 1500,2990
  rectangle net NetD48_2: 1600,1610 1695,1880
  rectangle net NetD49_2: 1710,1610 1880,1880
  rectangle net NetD49_2: 2870,1646.93 3150,1740
  rectangle net OUT1: 2870,1755 3115,1920
  rectangle net V_backlight: 7390,4966.93 7575,5075
  rectangle net NetD52_2: 8320,5175 8580,5240
  rectangle net NetD53_2: 8305,4970 8580,5165
  rectangle net NetD53_2: 11632.6,4490 11730,4760
  rectangle net NetD54_2: 11745.68,4490 11910,4765.68
  rectangle net NetD54_2: 12330,3826.93 12425,4100
  rectangle net NetD55_2: 12435,3826.93 12610,4100
  rectangle net NetD55_2: 12712.6,2720 12815,2990
  rectangle net NetD56_2: 12825,2720 12990,2991.26
  rectangle net NetD57_2: 11070,1845 11350,1920
  rectangle net NetD58_2: 11070,1648.19 11350,1835
  rectangle net NetD58_2: 10200,1648.19 10480,1745
  rectangle net OUT2: 10200,1760 10480,1920
  rectangle net V_backlight: 9642.6,4488.26 9715,4760
  rectangle net NetD60_2: 9725,4489.26 9920.81,4760.07
  rectangle net NetD60_2: 8932.6,3826.93 9015,4100
  rectangle net NetD61_2: 9025,3826.93 9210,4100
  rectangle net NetD61_2: 8552.6,2716.93 8635,2990
  rectangle net NetD62_2: 8645,2716.93 8830,2990
  rectangle net NetD63_2: 8932.6,1608.19 9105,1880
  rectangle net NetD62_2: 9115,1609.19 9210,1880
  rectangle net NetD64_2: 5012.6,1608.19 5190,1880
  rectangle net NetD63_2: 5210,1606.93 5290,1880
  rectangle net NetD64_2: 3740,1648.19 4020,1740
  rectangle net NetD65_2: 3740,1760 4020,1920
  rectangle net NetD65_2: 5382.6,2719.45 5475,2990
  rectangle net NetD66_2: 5485,2716.93 5660,2990
  rectangle net NetD66_2: 5000,3826.93 5090,4100
  rectangle net OUT3: 5105,3826.93 5280,4100
  region net NetC54_2: 7795,3840 7625,3840 7625,4290 7795,4290
  region net GND: 8695,4340 8265,4340 8265,4180 8695,4180
  region net GND: 7200,3580 7030,3580 7030,4630 7200,4630
  region net NetC54_2: 8076.35,4016 8004,4016 7977.65,4042.35 7977.65,4066.35 7945,4099 7690,4099 7690,4290 7910,4290 8020,4180 8020,4040 8028,4032 8076.35,4032
  region net 5V: 8706,4848 7220,4848 7220,4115 7455,4115 7455,4340 7817,4702 8706,4702
  region net 5V: 7450,4115 7235,4115 7235,4575 7455,4575
  region net V_backlight: 7585,3580 7585,4070 7225,4070 7225,3580
  region net GND: 7732,5334.85 7732,5354 7756,5378 7756,5585 7887,5716 8065,5716 8065,4873 8067,4871 8066,4870 7970,4870 7807,4870 7761,4916 7761,5247.3 7744.3,5264 7733,5264 7733,5286 7738.5,5286 7738.87,5286.38 7743.25,5282 7775,5282 7784.85,5282 7848,5218.85 7848,5194 7977.79,5194 7977.79,5383 7778,5383 7743,5348 7743,5334
  region net NetC28_2: 7685,5315 7686.2,5316.2 7751.2,5316.2 7763,5328 7827,5328 7859,5360 7955,5360 7955,5220 7880,5220 7810,5290 7760,5290 7760,5296.02 7751.02,5305 7685,5305
  region net VBOOST: 7705,5285 7705,5261 7640,5196 7640,5060 7745,5060 7745,5226 7713,5258 7713,5285
  region net VBOOST: 7713,5335 7713,5377 7735,5399 7735,5660 7678,5660 7678,5402 7703,5377 7703,5335
  region net NetC20_1: 4245.64,4721.34 4249.3,4725 4405,4725 4455,4775 4455,4835 4575,4835 4575,4655 4319.3,4655 4305,4669.3 4287.02,4687.29 4245.64,4687.29
  region net GND: 4075,4675 4285,4675 4315,4645 4575,4645 4575,4460 3994.88,4460 3994.88,4555 4030,4555 4075,4600
  region net 3V3: 4580,4445 3985,4445 3985,4520 3980,4525 3725,4525 3725,4295 4580,4295
  region net NetC22_2: 4058.98,4665 3715,4665 3715,4540 3960,4540 3990,4570 3990,4590 4035,4590 4060,4615
  region net 5V: 8205,4380 8205,4800 8207,4802 8709,4802 8709,4379.01
  region net NetC2_1: 3960,5195 3960,5435 4105,5435 4105,5622.23 4250,5622.23 4250,5565 4210,5525 4210,5195
  text ".Layer_Name" at 577,-858.49 h60

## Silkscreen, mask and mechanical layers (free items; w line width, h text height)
Top Overlay:
  drawing of 258 lines, arcs and shapes, not listed
  text "VBOOST" at 6701,5721 h40
  text "GND" at 7048,5721 h40
  text "5V" at 8568,5696 h40
  text "KL30+" at 3477,5687 h50
  text "KL30-" at 3170,5685 h50
  text "GND" at 2992,5613 h40
  text "GND" at 11016,5610 h40
  text "VIN" at 4468,5316 h40
  text "BAT" at 3647,5314 h40
  text "LEFT" at 4983,5113 h40
  text "RIGHT" at 9080,5105 h40
  text "3V3" at 5232,4523 h40
  text "Backlight" at 7378,3565 h40
  text "High Beam" at 6507,3553 h40
  text "Left" at 6627,3447 h40
  text "Safety Belt" at 6461,3354 h40
  text "Reverse" at 6562,3259 h40
  text "Park" at 7400,3257 h40
  text "SER_OUT" at 8221,3194 h40
  text "G1" at 6776,3148 h40
  text "PWM_Aud" at 5695,3141 h40
  text "PWM_BL" at 6587,3048 h40
  text "ADC" at 7606,3033 h40
  text "G2" at 7164,2943 h40
  text "O/D" at 13635,2902 h40
  text "Speed Control" at 238,2878 h40
  text "CLR" at 6756,2860 h40
  text "SER_IN" at 8240,2733 h40
  text "RCK" at 6765,2728 h40
  text "4 LOW" at 13595,2546 h40
  text "EN" at 8429,2534 h40
  text "ESP/BAS" at 356,2439 h40
  text "Open" at 868,2374 h40
  text "SRCK" at 8425,2332 h40
  text "ERR" at 6740,2330 h40
  text "Battery" at 883,2252 h40
  text "Open Fault" at 7318,2226 h40
  text "Short Fault" at 6477.22,2222 h40
  text "Charging" at 883,2163 h40
  text "GND" at 8479,2115 h40
  text "GND" at 5633,2111 h40
  text "4 LOCK" at 13585,2054 h40
  text "Short" at 725,1968 h40
  text "4WD" at 13222,1609 h40
  text "ETC" at 13719,1562 h40
  text "Transmission" at 139,1535 h40
  text "Safety Belt" at 658,1526 h40
  text "Temperature" at 150,1473 h40
  text "Diesel Preheat" at 13554,1111 h40
  text "4WD Auto" at 13122,1110 h40
  text "Front Fog" at 199,1088 h40
  text "ABS" at 823,1086 h40
  text "Fuel Moisture" at 13593,647 h40
  text "Engine Oil" at 1190,645 h40
  text "TOW/HAUL" at 12713,645 h40
  text "SVC 4WD" at 13206,645 h40
  text "Engine" at 748,643 h40
  text "Airbag" at 255,637 h40
  text "Malfunction" at 671,578 h40
  text "Pressure" at 1221,567 h40
  text "High Beam" at 5062,246 h40
  text "Fuel Level" at 5536,246 h40
  text "P" at 6145,246 h40
  text "R" at 6588,244 h40
  text "N" at 7028,242 h40
  text "D" at 7469,241 h40
  text "Engine Temperature" at 8129,240 h65
  text "ERS" at 7869,239 h40
  text "Fuel Tank" at 11800,175 h40
  text "ESC" at 12840,171 h40
  text "Tire Pressure" at 593,128 h40
  text "Cargo Light" at 2009,123 h40
  text "Brake Malfunction" at 1237,121 h40
  text ".Layer_Name" at 577,-858.49 h60
Bottom Overlay:
  text "-" at 3130,5509 h70
  text "+" at 3651,5503 h70
  text "AUDIO_OUT-" at 9841,5472 h60
  text "AUDIO_OUT+" at 9843,5376 h60
  text ".Layer_Name" at 577,-858.49 h60
Top Paste:
  text ".Layer_Name" at 577,-858.49 h60
Bottom Paste:
  text ".Layer_Name" at 577,-858.49 h60
Top Solder:
  text ".Layer_Name" at 577,-858.49 h60
  text ".Layer_Name" at 577,-858.49 h60
Bottom Solder:
  text ".Layer_Name" at 577,-858.49 h60
Drill Guide:
  text ".Layer_Name" at 577,-858.49 h60
M1 Board Outline:
  lines w10: 3185.93,5944.88 3200,5944.88 ; 0,0 0,4200 3179.92,5944.88 11032.68,5944.88 14212.6,4200 14212.6,0 0,0
  text ".Layer_Name" at 577,-858.49 h60
M2 Board Dimensions:
  rectangle: 125,-400 500,-275
  rectangle: 0,-275 125,-150
  lines w7: 0,-275 1000,-275 ; 125,-400 125,-150 ; 250,-400 250,-150 ; 500,-400 500,-150 ; 750,-400 750,-150 ; 0,-400 0,-150 1000,-150 1000,-400 0,-400
  text ".Layer_Name" at 577,-858.49 h60
M3 3D STEP Top:
  text ".Layer_Name" at 577,-858.49 h60
M4 3D STEP Bottom:
  text ".Layer_Name" at 577,-858.49 h60
M5 Assembly Top:
  lines w10: -292,-930.17 6308,-930.17 ; -292,-726.83 6310,-726.83 ; -292,-523.5 -292,-1133.5 3713,-1133.5 6310,-1133.5 6310,-523.5 -291.5,-523.5 -291.5,-1133.5 1284,-1133.5 ; 2173,-1133.5 2173,-523.5 ; 3440,-726.83 3440,-523.5 ; 4280,-726.83 4280,-523.5 ; 4902,-1140 4902,-937.17
  text "COMPONENTS MARKED 'DNP' SHOULD NOT BE POPULATED." at 1153.5,-318.5 h60
  text "ASSEMBLY VARIANT:" at 1153,-434 h60
  text ".VariantName" at 2189,-434 h60
  text "PCB VIEWED FROM TOP SIDE" at -228.5,-655.67 h60
  text "BOARD #:" at 2248,-655.67 h60
  text ".PRJ_Number" at 2793.5,-655.67 h60
  text "REV:" at 3638,-655.67 h60
  text ".PCB_Rev" at 3929.5,-655.67 h60
  text "SVN REV:" at 4476,-655.67 h60
  text ".VersionControl_RevNumber" at 4982,-655.67 h60
  text "PLOT NAME =" at -228.5,-1064.34 h60
  text ".plot_File_Name" at 577,-1064.34 h60
  text "GENERATED    :" at 2250,-1064.34 h60
  text ".Print_Date" at 3119.5,-1064.34 h60
  text ".Print_Time" at 3848.5,-1064.34 h60
  text "TEXAS INSTRUMENTS" at 5113,-1064.34 h60
M6 Assembly Bottom:
  lines w10: -292.5,-727.33 6309.5,-727.33 ; -290.5,-930.67 6309.5,-930.67 ; 1115.5,-1140.5 1115.5,-937.67 ; 1737.5,-727.33 1737.5,-524 ; 2577.5,-727.33 2577.5,-524 ; 3844.5,-1134 3844.5,-524 ; 4733.5,-1134 6309,-1134 6309,-524 -292.5,-524 -292.5,-1134 2304.5,-1134 6309.5,-1134 6309.5,-524
  text "COMPONENTS MARKED 'DNP' SHOULD NOT BE POPULATED." at 6102,-318 h60
  text ".VariantName" at 5058,-434 h60
  text "ASSEMBLY VARIANT:" at 6097,-434 h60
  text ".VersionControl_RevNumber" at 1035.5,-656.17 h60
  text "SVN REV:" at 1541.5,-656.17 h60
  text ".PCB_Rev" at 2088,-656.17 h60
  text "REV:" at 2379.5,-656.17 h60
  text ".PRJ_Number" at 3224,-656.17 h60
  text "BOARD #:" at 3769.5,-656.17 h60
  text "PCB VIEWED FROM BOTTOM SIDE" at 6246,-656.17 h60
  text "TEXAS INSTRUMENTS" at 904.5,-1064.84 h60
  text ".Print_Time" at 2169,-1064.84 h60
  text ".Print_Date" at 2898,-1064.84 h60
  text "GENERATED    :" at 3767.5,-1064.84 h60
  text ".plot_File_Name" at 5440.5,-1064.84 h60
  text "PLOT NAME =" at 6246,-1064.84 h60
M9 Title Sheet:
  drawing of 56 lines, arcs and shapes, not listed
  text "1" at 1058.34,13381.39 h70
  text "2" at 4384,13381.39 h70
  text "3" at 7714,13381.39 h70
  text "4" at 11049,13381.39 h70
  text "5" at 14374,13381.39 h70
  text "6" at 17709,13381.39 h70
  text "A" at -463,11603.39 h70
  text "A" at 19237,11603.39 h70
  text "B" at -463,7853.39 h70
  text "B" at 19237,7853.39 h70
  text "C" at -463,4103.39 h70
  text "C" at 19237,4103.39 h70
  text "D" at -463,353.39 h70
  text "D" at 19237,353.39 h70
  text "PROJECT TITLE:" at 16143,268.39 h45
  text ".PRJ_Title" at 16193,135.06 h70
  text "DESIGNED FOR:" at 16143,-32.61 h45
  text ".PRJ_Customer" at 16193,-172.61 h70
  text "FILE NAME:" at 16143,-332.61 h45
  text ".PCB_File_Name_No_Path" at 16193,-452.61 h70
  text "Texas Instruments (TI) and/or its licensors do not warrant the accuracy or completeness of this specification" at 11173.5,-614.45 h45
  text "ENGINEER:" at 16143,-622.61 h45
  text "LAYOUT BY:" at 17648,-622.61 h45
  text "or any information contained therein. TI and/or its licensors do not warrant that this design will meet" at 11128.51,-727.11 h45
  text ".PRJ_Engineer" at 16193,-777.6 h70
  text ".PCB_Layout" at 17698.5,-777.6 h70
  text "the specifications, will be suitable for your application or fit for any particular purpose, or will operate in" at 11128.51,-839.78 h45
  text ".Layer_Name" at 577,-858.49 h60
  text "ALTIUM DESIGNER VERSION:" at 17648,-932.61 h45
  text "an implementation. TI and/or its licensors do not warrant that the design is production worthy. You should" at 11128.51,-952.44 h45
  text "completely validate and test your design implementation to confirm the system functionality for your application." at 11173.5,-1065.11 h45
  text ".print_Scale" at 16193,-1065.94 h70
  text ".Application_BuildNumber" at 17698.5,-1065.94 h70
  text "1" at 1058.34,-1318.61 h70
  text "2" at 4384,-1318.61 h70
  text "3" at 7714,-1318.61 h70
  text "4" at 11049,-1318.61 h70
  text "5" at 14374,-1318.61 h70
  text "6" at 17709,-1318.61 h70
M10 Fab Notes:
  drawing of 189 lines, arcs and shapes, not listed
  text "DESIGN INFORMATION" at 17178.02,6365.17 h60
  text "MIN. TRACK WIDTH:" at 16533.46,6233.05 h60
  text "8" at 17629.7,6233.05 h60
  text "MIL" at 17784.46,6233.05 h60
  text "MIN. CLEARANCE:" at 16533.46,6108.92 h60
  text "0.2" at 17569.7,6108.93 h60
  text "mm" at 17784.46,6108.92 h60
  text "MIN. VIA PAD SIZE:" at 16533.46,5984.8 h60
  text "24" at 17599.71,5984.8 h60
  text "MIL" at 17784.46,5984.8 h60
  text "0.05mm (2MIL)" at 17228.46,5854.9 h60
  text "MINIMUM ANNULAR RING" at 16204.23,5846.67 h60
  text "EXTERNAL" at 17936.46,5846.67 h60
  text "PER" at 16404.23,5736.55 h60
  text "IPC-D-275 CLASS 2 LEVEL C" at 16624.23,5736.54 h60
  text "MIL, HOLES" at 18112.46,5636.07 h60
  text "+/-" at 17720,5627.48 h60
  text "+/-" at 18574,5627.48 h60
  text "REGISTRATION TOLERANCES:" at 16204.23,5626.42 h60
  text "METAL" at 17404,5626.42 h60
  text "5" at 17980.2,5626.42 h60
  text "3" at 18813.2,5626.42 h60
  text "MIL" at 18929.46,5626.42 h60
  text "HOLE SIZE TOLERANCE (UNLESS OTHERWISE SPECIFIED):" at 16204.23,5528.1 h60
  text "+/-" at 18574,5525.23 h60
  text "3" at 18813.2,5524.17 h60
  text "MIL" at 18929.46,5524.17 h60
  text "MATERIAL:" at 16129.46,5386.52 h60
  text "FR-4 High Tg" at 17115.9,5258 h60
  text "X" at 16971.46,5250.01 h60
  text "FR-408" at 16550.46,5245.49 h60
  text "OTHER" at 18038.46,5245.49 h60
  text "62 MIL (1.6mm) +/-10%" at 16870.56,5102.46 h60
  text "X" at 16750.46,5100.01 h60
  text "THICKNESS:" at 16204.23,5094.24 h60
  text "OTHER" at 18155.46,5094.24 h60
  text "TOLERANCE:" at 16204.23,4955.92 h60
  text "X" at 17052.46,4955.92 h60
  text "ANSI IPC-6012 TYPE 3 CLASS 2" at 17230.48,4955.92 h60
  text "OTHER +/-" at 17230.46,4811.73 h60
  text "BOW & TWIST:" at 16204.23,4666.54 h60
  text "X" at 17052.46,4666.54 h60
  text "ANSI IPC-6012 TYPE 3 CLASS 2" at 17230.48,4666.54 h60
  text "OTHER +/-" at 17230.46,4519.85 h60
  text "DRILLING:" at 16129.46,4389.23 h60
  text "NC_DRILL FILES" at 17890.46,4284.04 h60
  text "REFERENCE:" at 16204.23,4280.1 h60
  text "X" at 16861.46,4280.01 h60
  text "AS SHOWN" at 17039.46,4280.1 h60
  text "X" at 17762.46,4280.1 h60
  text "OTHER" at 18188.46,4137.85 h60
  text "PTH COPPER THICKNESS:" at 16203.91,4134.32 h60
  text "X" at 17343.14,4134.32 h60
  text "20-30 um" at 17471.14,4134.32 h60
  text "BOARD FINISH:" at 16129.46,3986.73 h60
  text "SILKSCREEN:" at 16284.68,3876.6 h60
  text "X" at 17242.46,3876.6 h60
  text "TOP" at 17359.46,3876.6 h60
  text "X" at 17752.46,3876.6 h60
  text "BOTTOM" at 17870.46,3876.6 h60
  text "SILKSCREEN COLOR:" at 16284.68,3721.41 h60
  text "X" at 17241.46,3721.41 h60
  text "WHITE" at 17359.46,3721.41 h60
  text "OTHER" at 17870.46,3721.41 h60
  text "X" at 17372.46,3577.96 h60
  text "GREEN" at 17490.46,3577.96 h60
  text "OTHER" at 18108.46,3577.96 h60
  text "SOLDER RESIST COLOR:" at 16284.68,3571.1 h60
  text "X" at 17372.46,3423.71 h60
  text "MATTE" at 17490.46,3423.71 h60
  text "SEMI-GLOSS" at 18108,3423.07 h60
  text "IMMERSION GOLD (ENIG)" at 17190.46,3250.94 h60
  text "ENEPIG" at 18528,3243.72 h60
  text "SURFACE FINISH:" at 16129.46,3242.72 h60
  text "X" at 17012.46,3242.72 h60
  text "IMM. TIN/SILVER OR EQUIV" at 16459,3105.4 h60
  text "OTHER" at 17890.46,3101.47 h60
  text "ARRAY/PANEL:" at 16129.46,2946.09 h60
  text "CUT AND TRIM PER M1 BOARD OUTLINE" at 17190.46,2937.87 h60
  text "N.C. ROUTE" at 17190.46,2801.9 h60
  text "X" at 17878.46,2801.9 h60
  text "V. SCORE" at 18056.46,2801.9 h60
  text "CERTIFICATION:" at 16129.46,2672.77 h60
  text "MATERIALS AND WORKMANSHIP FOR ALL PCBS" at 16854.46,2672.77 h60
  text "TO MEET OR EXCEED THE REQUIREMENTS OF:" at 16854.46,2578.71 h60
  text "X" at 16491.97,2450.08 h60
  text "ANSI IPC-A-600F CLASS ->" at 16619.96,2450.08 h60
  text "X" at 18267.97,2450.08 h60
  text "2" at 18377.96,2450.08 h60
  text "1" at 18062.96,2448.58 h60
  text "3" at 18731.96,2448.58 h60
  text "X" at 17303.97,2302.39 h60
  text "RoHS" at 17431.96,2302.39 h60
  text "OTHER" at 18076.36,2302.39 h60
  text "PER ORDER" at 18473.42,2302.39 h60
  text "ALL BOARDS MUST MEET OR EXCEED UL94-V0 REQUIREMENTS." at 16157,2148.57 h60
  text "PCB MUST BEAR THE UL94V-0 UL REGISTERED MATERIAL ID NUMBER" at 16157,2032.5 h60
  text "ADDITIONAL REQUIREMENTS:" at 16129.46,1863.08 h60
  text "MICROSECTION:" at 16204.23,1755.95 h60
  text "YES" at 17109.96,1755.95 h60
  text "REQUIRED" at 17971.46,1611.62 h60
  text "BARE BOARD ELEC. TEST:" at 16204.23,1608.76 h60
  text "NONE" at 17509.96,1608.76 h60
  text "X" at 17853.46,1608.76 h60
  text "PER ORDER" at 18563.46,1608.76 h60
  text "XX MIL VIAS REQUIRE NON-CONDUCTIVE FILL AND PLANARIZE" at 16372.38,1403.82 h59
  text "XX MIL VIAS REQUIRE CONDUCTIVE FILL AND PLANARIZE" at 16380.38,1299.84 h60
  text "OUTER XX MIL TRACES REQUIRE 50 OHM SINGLE-ENDED IMPEDANCE" at 16379.39,1136.46 h58
  text "LAYER 2 & 3 (INNER LAYERS) XX MIL WIDE, XX MIL SPACE / TRACES REQUIRE 100 OHM DIFFERENTIAL IMPEDANCE" at 16371.39,900.74 h60
  text ".Layer_Name" at 577,-858.49 h60
M11 Gerber Information:
  lines w10: -292,-930.17 6308,-930.17 ; -292,-726.83 6310,-726.83 ; -292,-523.5 -292,-1133.5 3713,-1133.5 6310,-1133.5 6310,-523.5 -291.5,-523.5 -291.5,-1133.5 1284,-1133.5 ; 2173,-1133.5 2173,-523.5 ; 3440,-726.83 3440,-523.5 ; 4280,-726.83 4280,-523.5 ; 4902,-1140 4902,-937.17
  text "ALL ARTWORK VIEWED FROM TOP SIDE" at -228.5,-655.67 h60
  text "BOARD #:" at 2248,-655.67 h60
  text ".PRJ_Number" at 2793.5,-655.67 h60
  text "REV:" at 3638,-655.67 h60
  text ".PCB_Rev" at 3929.5,-655.67 h60
  text "SVN REV:" at 4476,-655.67 h60
  text ".VersionControl_RevNumber" at 4982,-655.67 h60
  text "LAYER NAME =" at -228.5,-858.49 h60
  text "PLOT NAME =" at -228.5,-1064.34 h60
  text ".plot_File_Name" at 577,-1064.34 h60
  text "GENERATED    :" at 2250,-1064.34 h60
  text ".Print_Date" at 3119.5,-1064.34 h60
  text ".Print_Time" at 3848.5,-1064.34 h60
  text "TEXAS INSTRUMENTS" at 5113,-1064.34 h60
M12 Stackup:
  drawing of 399 lines, arcs and shapes, not listed
  text "Layer" at 14510.62,12009.46 h60
  text "Name" at 14920.53,12009.46 h60
  text "Material" at 15850.27,12009.46 h60
  text "Thickness" at 16740.03,12009.46 h60
  text "Constant" at 17389.87,12009.46 h60
  text "Board Layer Stack" at 17959.73,12009.46 h60
  text "1" at 14510.62,11889.46 h60
  text "Top Overlay" at 14920.53,11889.46 h60
  text "2" at 14510.62,11769.46 h60
  text "Top Solder" at 14920.53,11769.46 h60
  text "Solder Resist" at 15850.27,11769.46 h60
  text "0.40mil" at 16740.03,11769.46 h60
  text "3.5" at 17389.87,11769.46 h60
  text "3" at 14510.62,11649.46 h60
  text "Top Layer" at 14920.53,11649.46 h60
  text "Copper" at 15850.27,11649.46 h60
  text "1.90mil" at 16740.03,11649.46 h60
  text "4" at 14510.62,11529.46 h60
  text "Pre-Preg" at 14920.53,11529.46 h60
  text "1080-FR-4 370" at 15850.27,11529.46 h60
  text "11.80mil" at 16740.03,11529.46 h60
  text "4.2" at 17389.87,11529.46 h60
  text "5" at 14510.62,11409.46 h60
  text "GND" at 14920.53,11409.46 h60
  text "Copper" at 15850.27,11409.46 h60
  text "1.20mil" at 16740.03,11409.46 h60
  text "6" at 14510.62,11289.46 h60
  text "Core" at 14920.53,11289.46 h60
  text "FR4 370" at 15850.27,11289.46 h60
  text "31.00mil" at 16740.03,11289.46 h60
  text "4.2" at 17389.87,11289.46 h60
  text "7" at 14510.62,11169.46 h60
  text "5V" at 14920.53,11169.46 h60
  text "Copper" at 15850.27,11169.46 h60
  text "1.20mil" at 16740.03,11169.46 h60
  text "8" at 14510.62,11049.46 h60
  text "Pre-Preg" at 14920.53,11049.46 h60
  text "1080-FR4 370" at 15850.27,11049.46 h60
  text "11.80mil" at 16740.03,11049.46 h60
  text "4.2" at 17389.87,11049.46 h60
  text "9" at 14510.62,10929.46 h60
  text "Bottom Layer" at 14920.53,10929.46 h60
  text "Copper" at 15850.27,10929.46 h60
  text "1.90mil" at 16740.03,10929.46 h60
  text "10" at 14510.62,10809.46 h60
  text "Bottom Solder" at 14920.53,10809.46 h60
  text "Solder Resist" at 15850.27,10809.46 h60
  text "0.40mil" at 16740.03,10809.46 h60
  text "3.5" at 17389.87,10809.46 h60
  text "11" at 14510.62,10689.46 h60
  text "Bottom Overlay" at 14920.53,10689.46 h60
  text ".Layer_Name" at 577,-858.49 h60
M13 Component Bodies Top:
  text ".Layer_Name" at 577,-858.49 h60
M14 Component Bodies Bottom:
  text ".Layer_Name" at 577,-858.49 h60
M15 Courtyards Top:
  text ".Layer_Name" at 577,-858.49 h60
M16 Courtyards Bottom:
  text ".Layer_Name" at 577,-858.49 h60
